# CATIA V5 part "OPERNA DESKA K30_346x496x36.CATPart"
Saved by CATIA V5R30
Part number: OPERNA DESKA
Bounding box of the stored display mesh (mm): x 0 to 36, y -248 to 248, z -173 to 173
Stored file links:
  C:\Users\ondra\Desktop\PŘÍLOHA P III\CATIA\OPERNA DESKA K30_346x496x36.CATPart
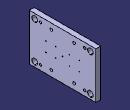
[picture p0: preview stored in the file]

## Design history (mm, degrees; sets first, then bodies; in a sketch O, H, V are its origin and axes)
Set1
  DatumSurface1 to DatumSurface22 "K30/346x"
  Plane1: type Offset, RefPlane yz-plane, Offset 36
  Join1: Elements (DatumSurface1; DatumSurface2; DatumSurface3; DatumSurface4; DatumSurface5; DatumSurface6; DatumSurface7; DatumSurface8; DatumSurface9; DatumSurface10; DatumSurface11; DatumSurface12; DatumSurface13; DatumSurface14; DatumSurface15; DatumSurface16; DatumSurface17; DatumSurface18; DatumSurface19; DatumSurface20; DatumSurface21; DatumSurface22)
Body1 (main body)
  DatumPoint1
  CloseSurface1: CloseElement Join1
  Sketch1 on {plane type Tangent, Support face of CloseSurface1, RefPoint vertex of DatumPoint1}, origin (119, -85, -130), H (0, 1, 0), V (0, 0, -1)
    point P1 (0, 0)
    reference projected point E1 (0, 0) from vertex of DatumPoint1
    coincidence: E1 P1
  Hole1: placed by Sketch1, at (36, -85, -130) direction (-1, 0, 0), diameter 20, through (limit type 6)
  DatumPoint2
  DatumPoint3
  Sketch2, origin (119, 0, 0), H (0, 1, 0), V (0, 0, -1), geometry linked from another document
  UserPattern1: of Hole1, copies 4, at the points of Sketch2
  Sketch3 on {plane type Tangent, Support face of CloseSurface1, RefPoint vertex of DatumPoint3}, origin (97, -125.2609, 36.7368), H (0, 1, 0), V (0, 0, -1)
    point P1 (0, 0)
    reference projected point E1 (0, 0) from vertex of DatumPoint3
    coincidence: E1 P1
  Hole2: placed by Sketch3, at (36, -125.2609, 36.7368) direction (-1, 0, 0), diameter 6.5, through (limit type 6)
  Sketch4, origin (97, 0, 0), H (0, 1, 0), V (0, 0, 1), geometry linked from another document
  Sketch5, origin (97, 0, 0), H (0, 1, 0), V (0, 0, 1), geometry linked from another document
  Sketch6, origin (97, 0, 0), H (0, 1, 0), V (0, 0, 1), geometry linked from another document
  DatumPoint4
  UserPattern2: of Hole2, copies 8, at the points of Sketch5
  Sketch7 on {plane type Tangent, Support face of CloseSurface1, RefPoint vertex of DatumPoint4}, origin (80, 0, 0), H (0, 1, 0), V (0, 0, -1)
    point P1 (0, 0)
    reference projected point E1 (0, 0) from vertex of DatumPoint4
    coincidence: E1 P1
  Hole3: placed by Sketch7, at (36, 0, 0) direction (-1, 0, 0), diameter 6.5, through (limit type 6)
